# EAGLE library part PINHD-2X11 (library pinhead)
PIN HEADER
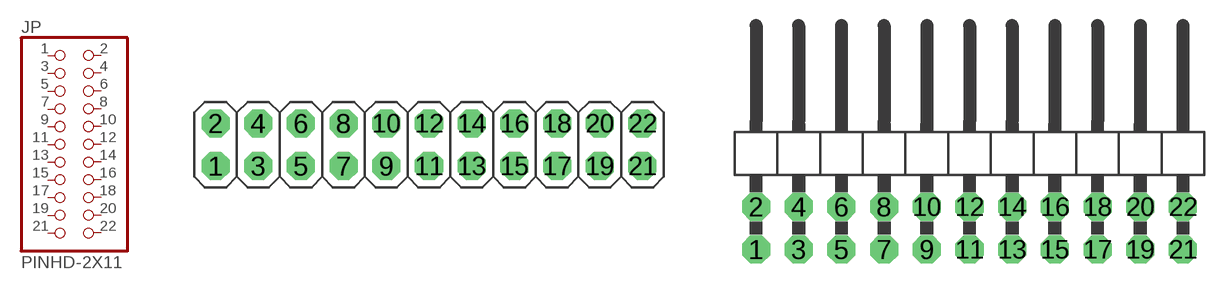
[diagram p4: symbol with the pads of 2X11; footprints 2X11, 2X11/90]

Designator prefix JP

## PINHD-2X11  [2X11]
1  1  pas
2  2  pas
3  3  pas
4  4  pas
5  5  pas
6  6  pas
7  7  pas
8  8  pas
9  9  pas
10  10  pas
11  11  pas
12  12  pas
13  13  pas
14  14  pas
15  15  pas
16  16  pas
17  17  pas
18  18  pas
19  19  pas
20  20  pas
21  21  pas
22  22  pas

## PINHD-2X11/90  [2X11/90]
Pads as for 2X11

## Footprint 2X11 (pad centres in mm)
PIN HEADER
drill 1.016 pad 1.67 octagon: 1 -12.7,-1.27; 2 -12.7,1.27; 3 -10.16,-1.27; 4 -10.16,1.27; 5 -7.62,-1.27; 6 -7.62,1.27; 7 -5.08,-1.27; 8 -5.08,1.27; 9 -2.54,-1.27; 10 -2.54,1.27; 11 0,-1.27; 12 0,1.27; 13 2.54,-1.27; 14 2.54,1.27; 15 5.08,-1.27; 16 5.08,1.27; 17 7.62,-1.27; 18 7.62,1.27; 19 10.16,-1.27; 20 10.16,1.27; 21 12.7,-1.27; 22 12.7,1.27

## Footprint 2X11/90 (pad centres in mm)
PIN HEADER
drill 1.016 pad 1.67 octagon: 1 -12.7,-6.35; 2 -12.7,-3.81; 3 -10.16,-6.35; 4 -10.16,-3.81; 5 -7.62,-6.35; 6 -7.62,-3.81; 7 -5.08,-6.35; 8 -5.08,-3.81; 9 -2.54,-6.35; 10 -2.54,-3.81; 11 0,-6.35; 12 0,-3.81; 13 2.54,-6.35; 14 2.54,-3.81; 15 5.08,-6.35; 16 5.08,-3.81; 17 7.62,-6.35; 18 7.62,-3.81; 19 10.16,-6.35; 20 10.16,-3.81; 21 12.7,-6.35; 22 12.7,-3.81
